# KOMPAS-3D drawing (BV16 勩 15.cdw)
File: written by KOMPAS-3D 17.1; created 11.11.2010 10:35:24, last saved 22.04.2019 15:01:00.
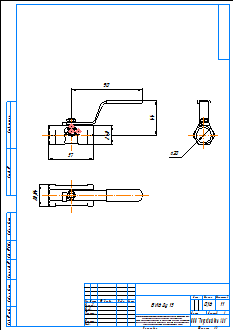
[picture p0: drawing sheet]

Sheet 1: A3, portrait

Title block, sheet 1: name: BV16 Ду 15; material: Внимание! Данный продукт является объектом авторского права ООО «Торговый Дом АДЛ». / Запрещается изменение, копирование, распространение / (в том числе путем копирования на другие сайты и ресурсы в Интернете) / или любое иное использование информации и объектов без предварительного / согласия правообладателя (ООО «Торговый Дом АДЛ»).; mass: 0,16; scale: 1:1; sheets: 1; organisation: ООО "Торговый дом АДЛ"; sheet format: A3; stored path: \\adlc.lan\data\АДЛ_ПКД\3D-модели\ADL production\Краны шаровые серии BV\BV16\KOMPAS 2D\BV16 Ду 15.cdw

Views: Спереди 1, Проекционный вид 2, Проекционный вид 3
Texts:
  user
  adl
Dimensions and other numbers on the sheet: 24,8; 57; 44; 90; 20; 28,64; 1:1; 1; 0,16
